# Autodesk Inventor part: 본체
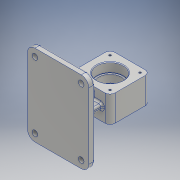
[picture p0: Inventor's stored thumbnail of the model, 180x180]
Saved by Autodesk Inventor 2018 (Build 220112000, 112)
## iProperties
Created: 2020-11
Part Number: 본체
Material: 알루미늄 6061
Document SubType Name: Modeling
Designer: 1class 3
Density: 2.7 g/cm^3
Appearance: 알루미늄 - 평지
Mass: 683.214 g
Surface Area: 542.794 cm^2
Volume: 253.042 cm^3
Author: 1class 3
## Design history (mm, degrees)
sketch "스케치1"
  geometry: L1 (-32, -32)-(32, -32); L2 (32, -32)-(32, 32); L3 (32, 32)-(-32, 32); L4 (-32, 32)-(-32, -32); L5 (-32, -32)-(32, 32); L6 (32, -32)-(-32, 32); 1 further point
  constraints: 12 end point, 2 midpoint, 2 parallel, 1 horizontal, 1 perpendicular
  dimensions: "d0" = 64 distance of L3.end L2.end; "d1" = 64 distance of L2.end L1.end
extrude "돌출1" new body sketch "스케치1" stored distance "d2" = 42; taper "d3" = 0 deg
fillet "모깎기1" dims "d4" = 8
sketch "스케치2"
  geometry: C1 r 18 at (0, 0); 1 further point
  constraints: 1 centre point, 1 coincident
  dimensions: "d5" = 36 diameter of C1
extrude "돌출2" cut sketch "스케치2" distance "d6" = 42; taper "d7" = 0 deg
sketch "스케치3"
  geometry: L1 (-24, 32)-(24, 32) reference; L2 (32, 24)-(32, -24) reference; L3 (24, -32)-(-24, -32) reference; L4 (-32, -24)-(-32, 24) reference; C1 r 21 at (0, 0); C2 r 18 at (0, 0) reference; A1 r 8 centre (-24, 24) between (-24, 32) and (-32, 24) reference; A2 r 8 centre (24, 24) between (32, 24) and (24, 32) reference; A3 r 8 centre (24, -24) between (24, -32) and (32, -24) reference; A4 r 8 centre (-24, -24) between (-32, -24) and (-24, -32) reference; 1 further point
  constraints: 1 centre point, 1 coincident
  dimensions: "d8" = 42 diameter of C1
extrude "돌출3" cut sketch "스케치3" distance "d9" = 15; taper "d10" = 0 deg
sketch "스케치4"
  geometry: L1 (32, 24)-(32, -24) reference; L2 (24, -32)-(-24, -32) reference; L3 (-32, -24)-(-32, 24) reference; L4 (-24, 32)-(24, 32) reference; C1 r 21 at (0, 0); C2 r 18 at (0, 0) reference; A1 r 8 centre (24, 24) between (32, 24) and (24, 32) reference; A2 r 8 centre (24, -24) between (24, -32) and (32, -24) reference; A3 r 8 centre (-24, -24) between (-32, -24) and (-24, -32) reference; A4 r 8 centre (-24, 24) between (-24, 32) and (-32, 24) reference; 1 further point
  constraints: 1 centre point, 1 coincident
  dimensions: "d11" = 42 diameter of C1
extrude "돌출4" cut sketch "스케치4" distance "d12" = 15; taper "d13" = 0 deg
fillet "모깎기2" dims "d14" = 0.3
chamfer "모따기1" distance "d15" = 1; stored, may be unused: second distance "d16" = 2, angle "d17" = 45 deg
sketch "스케치7"
  geometry: L1 (-24, -24)-(24, -24); L2 (24, -24)-(24, 24); L3 (24, 24)-(-24, 24); L4 (-24, 24)-(-24, -24); L5 (-24, -24)-(24, 24); L6 (24, -24)-(-24, 24); 5 further points
  constraints: 12 end point, 4 coincident, 2 midpoint, 2 parallel, 1 horizontal, 1 perpendicular
  dimensions: "d36" = 48 distance of L3.end L2.end; "d37" = 48 distance of L2.end L1.end
hole "구멍1" sketch "스케치7" at (-24, 24), (24, 24), (24, -24), (-24, -24) diameter "d38" = 3.242; stored, may be unused: countersink angle "d42" = 90 deg, drill point angle "d44" = 118 deg; dims "d39" = 8, "d40" = 4, "d41" = 2, "d43" = 10
node "작업 평면2"
sketch "스케치10"
  geometry: L1 (0, 0)-(62, 0); L2 (62, 0)-(62, -65); L3 (62, -65)-(0, -65); L4 (0, -65)-(0, 0); L5 (0, 0)-(62, 0); L6 (62, 0)-(62, 65); L7 (62, 65)-(0, 65); L8 (0, 65)-(0, 0); L9 (0, 65)-(-36, 65); L10 (-36, 65)-(-36, -65); L11 (-36, -65)-(0, -65); L12 (0, -65)-(0, 65)
  constraints: 24 end point, 6 parallel, 3 horizontal, 3 perpendicular
  dimensions: "d56" = 62 distance of L2.end L3.end; "d57" = 65 distance of L1.end L2.end; "d58" = 62 distance of L7.end L6.end; "d59" = 65 distance of L6.end L5.end; "d60" = 36 distance of L11.end L10.end; "d61" = 130 distance of L10.end L9.end
extrude "돌출8" join sketch "스케치10" distance "d62" = 10; taper "d63" = 0 deg
sketch "스케치11"
  geometry: L1 (20, -4)-(-20, -4); L2 (-20, -4)-(-20, 4); L3 (-20, 4)-(20, 4); L4 (20, 4)-(20, -4); L5 (20, -4)-(-20, 4); L6 (-20, -4)-(20, 4); L7 (4, -17)-(-4, -17); L8 (-4, -17)-(-4, 17); L9 (-4, 17)-(4, 17); L10 (4, 17)-(4, -17); L11 (4, -17)-(-4, 17); L12 (-4, -17)-(4, 17); 1 further point
  constraints: 24 end point, 4 midpoint, 4 parallel, 2 horizontal, 2 perpendicular
  dimensions: "d64" = 40 distance of L2.end L3.end; "d65" = 8 distance of L1.end L2.end; "d66" = 8 distance of L8.end L9.end; "d67" = 34 distance of L7.end L8.end
extrude "돌출9" join sketch "스케치11" stored distance "d68" = 10; taper "d69" = 0 deg
fillet "모깎기6" dims "d70" = 3
fillet "모깎기7" dims "d71" = 12
sketch "스케치12"
  geometry: C1 r 4.5 at (-50, -53); C2 r 4.5 at (-50, 53); C3 r 4.5 at (24, 53); C4 r 4.5 at (24, -53); A1 r 12 centre (-50, -53) between (-62, -53) and (-50, -65) reference; A2 r 12 centre (-50, 53) between (-50, 65) and (-62, 53) reference; A3 r 12 centre (24, 53) between (36, 53) and (24, 65) reference; A4 r 12 centre (24, -53) between (24, -65) and (36, -53) reference; 1 further point
  constraints: 4 centre point, 4 coincident
  dimensions: "d72" = 9 diameter of C1; "d73" = 9 diameter of C2; "d74" = 9 diameter of C3; "d75" = 9 diameter of C4
extrude "돌출10" cut sketch "스케치12" distance "d76" = 10; taper "d77" = 0 deg
fillet "모깎기8" dims "d78" = 3
sketch "스케치14"
  geometry: L1 (24, 65)-(-50, 65) reference; L2 (-62, 53)-(-62, -53) reference; 2 further points
  constraints: 1 other
  dimensions: "d83" = 65 distance from line of L1 point (-52, 0); "d84" = 10 distance from line of L2 point (-52, 0)
feature "엠보싱3" sketch "스케치14" dims "d85" = 0.5, "d86" = 0
node "솔리드1"
mirror "미러1"
node "절단 모서리 투영1"
node "절단 모서리 투영2"
